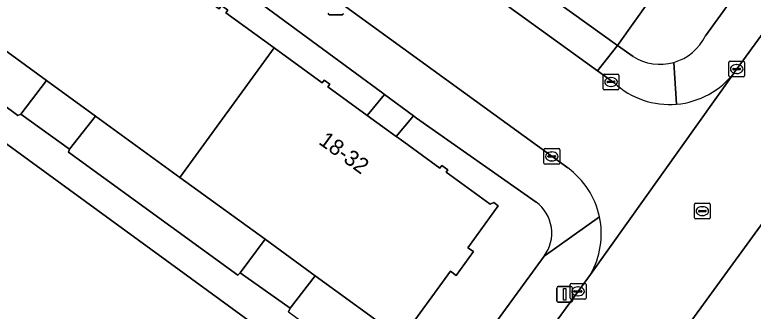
# Model space of a CAD drawing. Extents: x 160102 to 160934, y 382045 to 382923.
# Drawn here: x 160345.72 to 160392.53, y 382406.82 to 382425.59 of the extents above; entities that cross this region are included whole.
import ezdxf

# ---------------------------------------------------------------- set-up
doc = ezdxf.new("R2010")
doc.units = 0
for name, color, linetype in [('IMGEO_Groenvoorziening', 7, 'Continuous'), ('IMGEO_Kolk', 7, 'Continuous'), ('IMGEO_Lichtmast', 7, 'Continuous'), ('IMGEO_Pand', 7, 'Continuous'), ('IMGEO_Pand_nummerreeks', 7, 'Continuous'), ('IMGEO_Parkeervlak_open', 7, 'Continuous'), ('IMGEO_Rijbaan_lokaal_open', 7, 'Continuous'), ('IMGEO_Rioolput', 7, 'Continuous'), ('IMGEO_Voetpad_gesloten', 7, 'Continuous'), ('IMGEO_Voetpad_op_trap', 7, 'Continuous'), ('IMGEO_Voetpad_open', 7, 'Continuous')]:
    doc.layers.add(name, color=color, linetype=linetype)

msp = doc.modelspace()

# ---------------------------------------------------------------- linework, layer by layer
at = {"layer": 'IMGEO_Groenvoorziening'}
for points in [[(160422.2, 382470.206), (160417.015, 382473.964), (160416.838, 382473.717), (160390.944, 382492.372), (160384.801, 382491.609), (160352.064, 382446.689), (160359.103, 382441.461), (160362.329, 382445.915), (160366.484, 382451.639), (160368.953, 382449.846), (160371.422, 382448.054), (160373.891, 382446.261), (160376.36, 382444.469), (160378.829, 382442.676), (160381.297, 382440.884), (160383.766, 382439.091), (160386.235, 382437.299), (160388.704, 382435.507), (160391.173, 382433.714), (160387.018, 382427.991), (160383.929, 382423.658), (160384.908, 382422.956)], [(160389.495, 382424.254), (160422.478, 382469.715)], [(160370.829, 382398.747), (160336.272, 382423.908), (160301.535, 382376.068), (160301.385, 382375.861), (160326.781, 382357.302), (160333.47, 382352.414)], [(160378.769, 382413.727), (160371.177, 382419.054), (160370.988, 382419.193), (160369.885, 382417.893), (160370.139, 382417.709), (160372.658, 382415.881), (160372.787, 382416.059), (160373.175, 382415.778), (160373.062, 382415.622), (160375.845, 382413.602), (160376.08, 382413.707), (160376.369, 382413.498), (160374.443, 382410.845), (160374.79, 382410.593), (160373.701, 382409.093), (160373.327, 382409.365), (160370.23, 382405.098), (160364.767, 382409.063), (160363.18, 382407.011), (160363.061, 382406.781), (160371.989, 382400.333), (160379.276, 382410.307)]]:
    msp.add_lwpolyline(points, dxfattribs=at)
for points in [[(160345.836, 382431.539), (160346.277, 382431.219), (160348.196, 382433.864), (160348.496, 382433.646), (160348.355, 382433.452), (160351.228, 382431.367), (160351.397, 382431.599), (160351.776, 382431.324), (160351.609, 382431.094), (160354.123, 382429.27), (160355.13, 382430.78), (160346.323, 382437.183), (160344.086, 382434.199), (160337.524, 382425.446), (160345.91, 382419.22), (160346.099, 382419.291), (160347.73, 382421.428), (160342.062, 382425.541), (160345.171, 382429.825), (160344.791, 382430.1)], [(160357.258, 382429.311), (160356.176, 382427.78), (160358.668, 382425.971), (160358.82, 382426.179), (160359.222, 382425.887), (160359.103, 382425.723), (160362.154, 382423.509), (160365.205, 382421.294), (160365.329, 382421.464), (160365.688, 382421.204), (160365.562, 382421.031), (160368.056, 382419.221), (160369.144, 382420.555), (160369.038, 382420.633)], [(160356.188, 382415.289), (160350.837, 382419.173), (160349.192, 382417.077), (160349.132, 382416.887), (160359.858, 382409.104), (160359.997, 382409.254), (160361.58, 382411.376)]]:
    msp.add_lwpolyline(points, close=True, dxfattribs=at)
for centre, radius, start, end in [((160386.618, 382425.663), 3.204, 285.8122, 333.9001), ((160386.619, 382425.659), 3.199, 237.6621, 285.817), ((160377.313, 382411.764), 2.444, 323.4216, 53.4433)]:
    msp.add_arc(centre, radius, start, end, dxfattribs=at)
at = {"layer": 'IMGEO_Kolk'}
for p, q in [((160390.981, 382421.731), (160390.981, 382422.583)), ((160391.056, 382422.657), (160391.908, 382422.657)), ((160391.469, 382422.437), (160391.494, 382422.437)), ((160391.982, 382422.583), (160391.982, 382421.731)), ((160391.24, 382422.151), (160391.24, 382422.163)), ((160391.678, 382422.114), (160391.28, 382422.114)), ((160391.283, 382422.2), (160391.681, 382422.2)), ((160391.724, 382422.163), (160391.724, 382422.151)), ((160383.011, 382420.915), (160383.011, 382421.767)), ((160383.086, 382421.841), (160383.938, 382421.841)), ((160383.499, 382421.621), (160383.524, 382421.621)), ((160384.012, 382421.767), (160384.012, 382420.915)), ((160391.908, 382421.657), (160391.056, 382421.657)), ((160391.492, 382421.877), (160391.467, 382421.877)), ((160383.27, 382421.335), (160383.27, 382421.347)), ((160383.708, 382421.298), (160383.31, 382421.298)), ((160383.313, 382421.384), (160383.711, 382421.384)), ((160383.522, 382421.061), (160383.497, 382421.061)), ((160383.754, 382421.347), (160383.754, 382421.335)), ((160383.938, 382420.841), (160383.086, 382420.841)), ((160379.257, 382416.199), (160379.257, 382417.051)), ((160379.332, 382417.125), (160380.184, 382417.125)), ((160379.745, 382416.905), (160379.77, 382416.905)), ((160380.258, 382417.051), (160380.258, 382416.199)), ((160379.516, 382416.619), (160379.516, 382416.631)), ((160379.954, 382416.582), (160379.556, 382416.582)), ((160379.559, 382416.668), (160379.957, 382416.668)), ((160379.768, 382416.345), (160379.743, 382416.345)), ((160380, 382416.631), (160380, 382416.619)), ((160380.184, 382416.125), (160379.332, 382416.125)), ((160380.926, 382407.653), (160380.926, 382408.505)), ((160381.001, 382408.579), (160381.853, 382408.579)), ((160381.927, 382408.505), (160381.927, 382407.653)), ((160381.185, 382408.073), (160381.185, 382408.085)), ((160381.623, 382408.036), (160381.225, 382408.036)), ((160381.228, 382408.122), (160381.626, 382408.122)), ((160381.414, 382408.359), (160381.439, 382408.359)), ((160381.669, 382408.085), (160381.669, 382408.073)), ((160381.853, 382407.579), (160381.001, 382407.579)), ((160381.437, 382407.799), (160381.412, 382407.799))]:
    msp.add_line(p, q, dxfattribs=at)
for points in [[(160390.981, 382421.731), (160390.981, 382422.583)], [(160391.056, 382422.657), (160391.908, 382422.657)], [(160391.982, 382422.583), (160391.982, 382421.731)], [(160383.011, 382420.915), (160383.011, 382421.767)], [(160383.086, 382421.841), (160383.938, 382421.841)], [(160384.012, 382421.767), (160384.012, 382420.915)], [(160391.908, 382421.657), (160391.056, 382421.657)], [(160383.938, 382420.841), (160383.086, 382420.841)], [(160379.257, 382416.199), (160379.257, 382417.051)], [(160379.332, 382417.125), (160380.184, 382417.125)], [(160380.258, 382417.051), (160380.258, 382416.199)], [(160380.184, 382416.125), (160379.332, 382416.125)], [(160380.926, 382407.653), (160380.926, 382408.505)], [(160381.001, 382408.579), (160381.853, 382408.579)], [(160381.927, 382408.505), (160381.927, 382407.653)], [(160381.853, 382407.579), (160381.001, 382407.579)]]:
    msp.add_lwpolyline(points, dxfattribs=at)
for centre, radius, start, end in [((160391.058, 382422.581), 0.0765, 91.552, 178.448), ((160391.058, 382422.581), 0.0765, 91.552, 178.448), ((160391.906, 382422.581), 0.0765, 1.552, 88.448), ((160391.906, 382422.581), 0.0765, 1.552, 88.448), ((160391.28, 382422.16), 0.0403, 85.8775, 175.7526), ((160391.277, 382422.15), 0.0366, 178.938, 274.7102), ((160391.681, 382422.157), 0.043, 264.8664, 352.4533), ((160391.685, 382422.162), 0.0386, 1.7309, 96.639), ((160383.088, 382421.765), 0.0765, 91.552, 178.448), ((160383.088, 382421.765), 0.0765, 91.552, 178.448), ((160383.936, 382421.765), 0.0765, 1.552, 88.448), ((160383.936, 382421.765), 0.0765, 1.552, 88.448), ((160391.058, 382421.733), 0.0765, 181.552, 268.448), ((160391.058, 382421.733), 0.0765, 181.552, 268.448), ((160391.906, 382421.733), 0.0765, 271.552, 358.448), ((160391.906, 382421.733), 0.0765, 271.552, 358.448), ((160383.31, 382421.344), 0.0403, 85.8775, 175.7526), ((160383.307, 382421.334), 0.0366, 178.938, 274.7102), ((160383.711, 382421.341), 0.043, 264.8664, 352.4533), ((160383.715, 382421.346), 0.0386, 1.7309, 96.639), ((160383.088, 382420.917), 0.0765, 181.552, 268.448), ((160383.088, 382420.917), 0.0765, 181.552, 268.448), ((160383.936, 382420.917), 0.0765, 271.552, 358.448), ((160383.936, 382420.917), 0.0765, 271.552, 358.448), ((160379.334, 382417.049), 0.0765, 91.552, 178.448), ((160379.334, 382417.049), 0.0765, 91.552, 178.448), ((160380.182, 382417.049), 0.0765, 1.552, 88.448), ((160380.182, 382417.049), 0.0765, 1.552, 88.448), ((160379.556, 382416.628), 0.0403, 85.8775, 175.7526), ((160379.553, 382416.618), 0.0366, 178.938, 274.7102), ((160379.957, 382416.625), 0.043, 264.8664, 352.4533), ((160379.961, 382416.63), 0.0386, 1.7309, 96.639), ((160379.334, 382416.201), 0.0765, 181.552, 268.448), ((160379.334, 382416.201), 0.0765, 181.552, 268.448), ((160380.182, 382416.201), 0.0765, 271.552, 358.448), ((160380.182, 382416.201), 0.0765, 271.552, 358.448), ((160381.003, 382408.503), 0.0765, 91.552, 178.448), ((160381.003, 382408.503), 0.0765, 91.552, 178.448), ((160381.851, 382408.503), 0.0765, 1.552, 88.448), ((160381.851, 382408.503), 0.0765, 1.552, 88.448), ((160381.225, 382408.082), 0.0403, 85.8775, 175.7526), ((160381.222, 382408.072), 0.0366, 178.938, 274.7102), ((160381.626, 382408.079), 0.043, 264.8664, 352.4533), ((160381.63, 382408.084), 0.0386, 1.7309, 96.639), ((160381.003, 382407.655), 0.0765, 181.552, 268.448), ((160381.003, 382407.655), 0.0765, 181.552, 268.448), ((160381.851, 382407.655), 0.0765, 271.552, 358.448), ((160381.851, 382407.655), 0.0765, 271.552, 358.448)]:
    msp.add_arc(centre, radius, start, end, dxfattribs=at)
for centre, major_axis, ratio, start_param, end_param in [((160391.468, 382422.157), (-0.387, 0.002), 0.722429, 4.712389, 7.853982), ((160391.493, 382422.157), (-0.39, 0.002), 0.717154, 1.570796, 4.712389), ((160383.498, 382421.341), (-0.387, 0.002), 0.722429, 4.712389, 7.853982), ((160383.523, 382421.341), (-0.39, 0.002), 0.717154, 1.570796, 4.712389), ((160379.744, 382416.625), (-0.387, 0.002), 0.722429, 4.712389, 7.853982), ((160379.769, 382416.625), (-0.39, 0.002), 0.717154, 1.570796, 4.712389), ((160381.413, 382408.079), (-0.387, 0.002), 0.722429, 4.712389, 7.853982), ((160381.438, 382408.079), (-0.39, 0.002), 0.717154, 1.570796, 4.712389)]:
    msp.add_ellipse(centre, major_axis=major_axis, ratio=ratio, start_param=start_param, end_param=end_param, dxfattribs=at)
at = {"layer": 'IMGEO_Lichtmast'}
for p, q in [((160366.461, 382425.594), (160365.671, 382425.594)), ((160365.671, 382425.594), (160366.461, 382425.594)), ((160380.171, 382408.386), (160380.961, 382408.386)), ((160380.961, 382408.386), (160380.171, 382408.386)), ((160380.071, 382407.486), (160380.071, 382408.286)), ((160380.071, 382408.286), (160380.071, 382407.486)), ((160381.061, 382408.286), (160381.061, 382407.486)), ((160381.061, 382407.486), (160381.061, 382408.286)), ((160380.961, 382407.386), (160380.171, 382407.386)), ((160380.171, 382407.386), (160380.961, 382407.386))]:
    msp.add_line(p, q, dxfattribs=at)
msp.add_lwpolyline([(160380.491, 382408.261), (160380.641, 382408.261), (160380.641, 382407.511), (160380.491, 382407.511), (160380.491, 382408.261)], dxfattribs=at)
for centre, start, end in [((160365.671, 382425.694), 180, 270), ((160365.671, 382425.694), 180, 270), ((160366.461, 382425.694), 270, 0), ((160366.461, 382425.694), 270, 0), ((160380.171, 382408.286), 90, 180), ((160380.171, 382408.286), 90, 180), ((160380.961, 382408.286), 0, 90), ((160380.961, 382408.286), 360, 90), ((160380.171, 382407.486), 180, 270), ((160380.171, 382407.486), 180, 270), ((160380.961, 382407.486), 270, 0), ((160380.961, 382407.486), 270, 0)]:
    msp.add_arc(centre, 0.1, start, end, dxfattribs=at)
at = {"layer": 'IMGEO_Pand'}
for points in [[(160356.176, 382427.78), (160354.123, 382429.27), (160351.609, 382431.094), (160351.776, 382431.324), (160351.397, 382431.599), (160351.228, 382431.367), (160348.355, 382433.452), (160348.496, 382433.646), (160348.196, 382433.864), (160346.277, 382431.219), (160345.836, 382431.539), (160344.791, 382430.1), (160345.171, 382429.825), (160342.062, 382425.541), (160347.73, 382421.428), (160350.837, 382419.173), (160356.188, 382415.289), (160362.154, 382423.509), (160359.103, 382425.723), (160359.222, 382425.887), (160358.82, 382426.179), (160358.668, 382425.971)], [(160370.139, 382417.709), (160369.885, 382417.893), (160368.056, 382419.221), (160365.562, 382421.031), (160365.688, 382421.204), (160365.329, 382421.464), (160365.205, 382421.294), (160362.154, 382423.509), (160356.188, 382415.289), (160361.58, 382411.376), (160364.767, 382409.063), (160370.23, 382405.098), (160373.327, 382409.365), (160373.701, 382409.093), (160374.79, 382410.593), (160374.443, 382410.845), (160376.369, 382413.498), (160376.08, 382413.707), (160375.845, 382413.602), (160373.062, 382415.622), (160373.175, 382415.778), (160372.787, 382416.059), (160372.658, 382415.881)]]:
    msp.add_lwpolyline(points, close=True, dxfattribs=at)
at = {"layer": 'IMGEO_Parkeervlak_open'}
msp.add_lwpolyline([(160374.674, 382436.953), (160372.205, 382438.745), (160369.736, 382440.538), (160367.267, 382442.33), (160364.798, 382444.123), (160362.329, 382445.915), (160359.103, 382441.461), (160383.929, 382423.658), (160387.018, 382427.991), (160384.549, 382429.783), (160382.08, 382431.576), (160379.611, 382433.368), (160377.142, 382435.161)], close=True, dxfattribs=at)
at = {"layer": 'IMGEO_Rijbaan_lokaal_open'}
for points in [[(160449.428, 382489.694), (160443.452, 382493.376), (160443.22, 382493.058), (160433.188, 382479.332), (160391.333, 382421.95), (160391.318, 382421.917), (160382.213, 382409.153), (160345.726, 382359.174), (160350.937, 382354.514), (160401.868, 382424.419), (160401.997, 382424.596), (160402.036, 382424.669), (160410.851, 382436.796), (160448.923, 382489.003)], [(160333.601, 382450.126), (160348.555, 382439.273), (160380.766, 382415.895)], [(160383.708, 382421.284), (160382.647, 382422.051), (160357.942, 382439.895)], [(160382.213, 382409.153), (160391.318, 382421.917), (160391.333, 382421.95)]]:
    msp.add_lwpolyline(points, dxfattribs=at)
for centre, radius, start, end in [((160387.219, 382425.084), 5.172, 274.9776, 322.698), ((160387.217, 382425.087), 5.175, 227.303, 274.9957), ((160377.726, 382411.715), 5.169, 12.1278, 53.9694), ((160377.728, 382411.717), 5.166, 330.2476, 12.1137)]:
    msp.add_arc(centre, radius, start, end, dxfattribs=at)
at = {"layer": 'IMGEO_Rioolput'}
for p, q in [((160388.799, 382412.736), (160388.799, 382413.588)), ((160388.874, 382413.662), (160389.726, 382413.662)), ((160389.8, 382413.588), (160389.8, 382412.736)), ((160389.058, 382413.156), (160389.058, 382413.168)), ((160389.496, 382413.119), (160389.098, 382413.119)), ((160389.101, 382413.205), (160389.499, 382413.205)), ((160389.287, 382413.442), (160389.312, 382413.442)), ((160389.542, 382413.168), (160389.542, 382413.156)), ((160389.726, 382412.662), (160388.874, 382412.662)), ((160389.31, 382412.882), (160389.285, 382412.882))]:
    msp.add_line(p, q, dxfattribs=at)
for points in [[(160388.799, 382412.736), (160388.799, 382413.588)], [(160388.874, 382413.662), (160389.726, 382413.662)], [(160389.8, 382413.588), (160389.8, 382412.736)], [(160389.726, 382412.662), (160388.874, 382412.662)]]:
    msp.add_lwpolyline(points, dxfattribs=at)
for centre, radius, start, end in [((160388.876, 382413.586), 0.0765, 91.552, 178.448), ((160388.876, 382413.586), 0.0765, 91.552, 178.448), ((160389.724, 382413.586), 0.0765, 1.552, 88.448), ((160389.724, 382413.586), 0.0765, 1.552, 88.448), ((160389.098, 382413.165), 0.0403, 85.8775, 175.7526), ((160389.095, 382413.155), 0.0366, 178.938, 274.7102), ((160389.499, 382413.162), 0.043, 264.8664, 352.4533), ((160389.503, 382413.167), 0.0386, 1.7309, 96.639), ((160388.876, 382412.738), 0.0765, 181.552, 268.448), ((160388.876, 382412.738), 0.0765, 181.552, 268.448), ((160389.724, 382412.738), 0.0765, 271.552, 358.448), ((160389.724, 382412.738), 0.0765, 271.552, 358.448)]:
    msp.add_arc(centre, radius, start, end, dxfattribs=at)
for centre, major_axis, ratio, start_param, end_param in [((160389.286, 382413.162), (-0.387, 0.002), 0.722429, 4.712389, 7.853982), ((160389.311, 382413.162), (-0.39, 0.002), 0.717154, 1.570796, 4.712389)]:
    msp.add_ellipse(centre, major_axis=major_axis, ratio=ratio, start_param=start_param, end_param=end_param, dxfattribs=at)
at = {"layer": 'IMGEO_Voetpad_gesloten'}
msp.add_lwpolyline([(160369.144, 382420.555), (160368.056, 382419.221), (160369.885, 382417.893), (160370.988, 382419.193)], close=True, dxfattribs=at)
at = {"layer": 'IMGEO_Voetpad_op_trap'}
for points in [[(160347.73, 382421.428), (160346.099, 382419.291), (160349.192, 382417.077), (160350.837, 382419.173)], [(160361.58, 382411.376), (160359.997, 382409.254), (160363.18, 382407.011), (160364.767, 382409.063)]]:
    msp.add_lwpolyline(points, close=True, dxfattribs=at)
at = {"layer": 'IMGEO_Voetpad_open'}
for points in [[(160433.916, 382483.104), (160430.297, 382480.492), (160423.32, 382470.875), (160422.478, 382469.715), (160389.495, 382424.254)], [(160391.333, 382421.95), (160433.188, 382479.332)], [(160380.766, 382415.895), (160348.555, 382439.273), (160333.601, 382450.126)], [(160330.141, 382444.298), (160342.342, 382435.462), (160344.086, 382434.199), (160346.323, 382437.183), (160355.13, 382430.78), (160357.258, 382429.311), (160369.038, 382420.633), (160369.144, 382420.555), (160370.988, 382419.193), (160371.177, 382419.054), (160378.769, 382413.727)], [(160363.061, 382406.781), (160363.18, 382407.011), (160359.997, 382409.254), (160359.858, 382409.104), (160349.132, 382416.887), (160349.192, 382417.077), (160346.099, 382419.291), (160345.91, 382419.22), (160337.524, 382425.446), (160344.086, 382434.199), (160342.342, 382435.462), (160336.971, 382427.863), (160336.63, 382428.051), (160334.297, 382424.828), (160334.588, 382424.579), (160326.893, 382413.858), (160326.472, 382414.075), (160324.208, 382410.933), (160324.45, 382410.594), (160316.804, 382399.911)], [(160401.997, 382424.596), (160401.868, 382424.419), (160350.937, 382354.514), (160347.546, 382349.9), (160347.076, 382350.22), (160346.901, 382350.349)], [(160301.535, 382376.068), (160336.272, 382423.908), (160370.829, 382398.747)], [(160384.908, 382422.956), (160383.929, 382423.658), (160382.647, 382422.051), (160383.708, 382421.284)], [(160387.491, 382422.581), (160387.668, 382419.932)], [(160387.668, 382419.932), (160387.491, 382422.581)], [(160382.779, 382412.801), (160379.276, 382410.307), (160371.989, 382400.333), (160370.829, 382398.747), (160343.422, 382361.234), (160337.389, 382352.977), (160335.916, 382349.031)], [(160379.276, 382410.307), (160382.779, 382412.801)], [(160339.751, 382350.99), (160345.726, 382359.174), (160382.213, 382409.153)]]:
    msp.add_lwpolyline(points, dxfattribs=at)
msp.add_lwpolyline([(160382.647, 382422.051), (160383.929, 382423.658), (160359.103, 382441.461), (160357.942, 382439.895)], close=True, dxfattribs=at)
for centre, radius, start, end in [((160386.618, 382425.663), 3.204, 285.8122, 333.9001), ((160386.619, 382425.659), 3.199, 237.6621, 285.817), ((160387.219, 382425.084), 5.172, 274.9776, 322.698), ((160387.217, 382425.087), 5.175, 227.303, 274.9957), ((160377.726, 382411.715), 5.169, 12.1278, 53.9694), ((160377.313, 382411.764), 2.444, 323.4216, 53.4433), ((160377.728, 382411.717), 5.166, 330.2476, 12.1137)]:
    msp.add_arc(centre, radius, start, end, dxfattribs=at)

# ---------------------------------------------------------------- texts
at = {"layer": 'IMGEO_Pand_nummerreeks'}
msp.add_text('18-32', height=1, rotation=324.1099, dxfattribs=at).set_placement((160364.922, 382417.458))

doc.saveas('drawing.dxf')
